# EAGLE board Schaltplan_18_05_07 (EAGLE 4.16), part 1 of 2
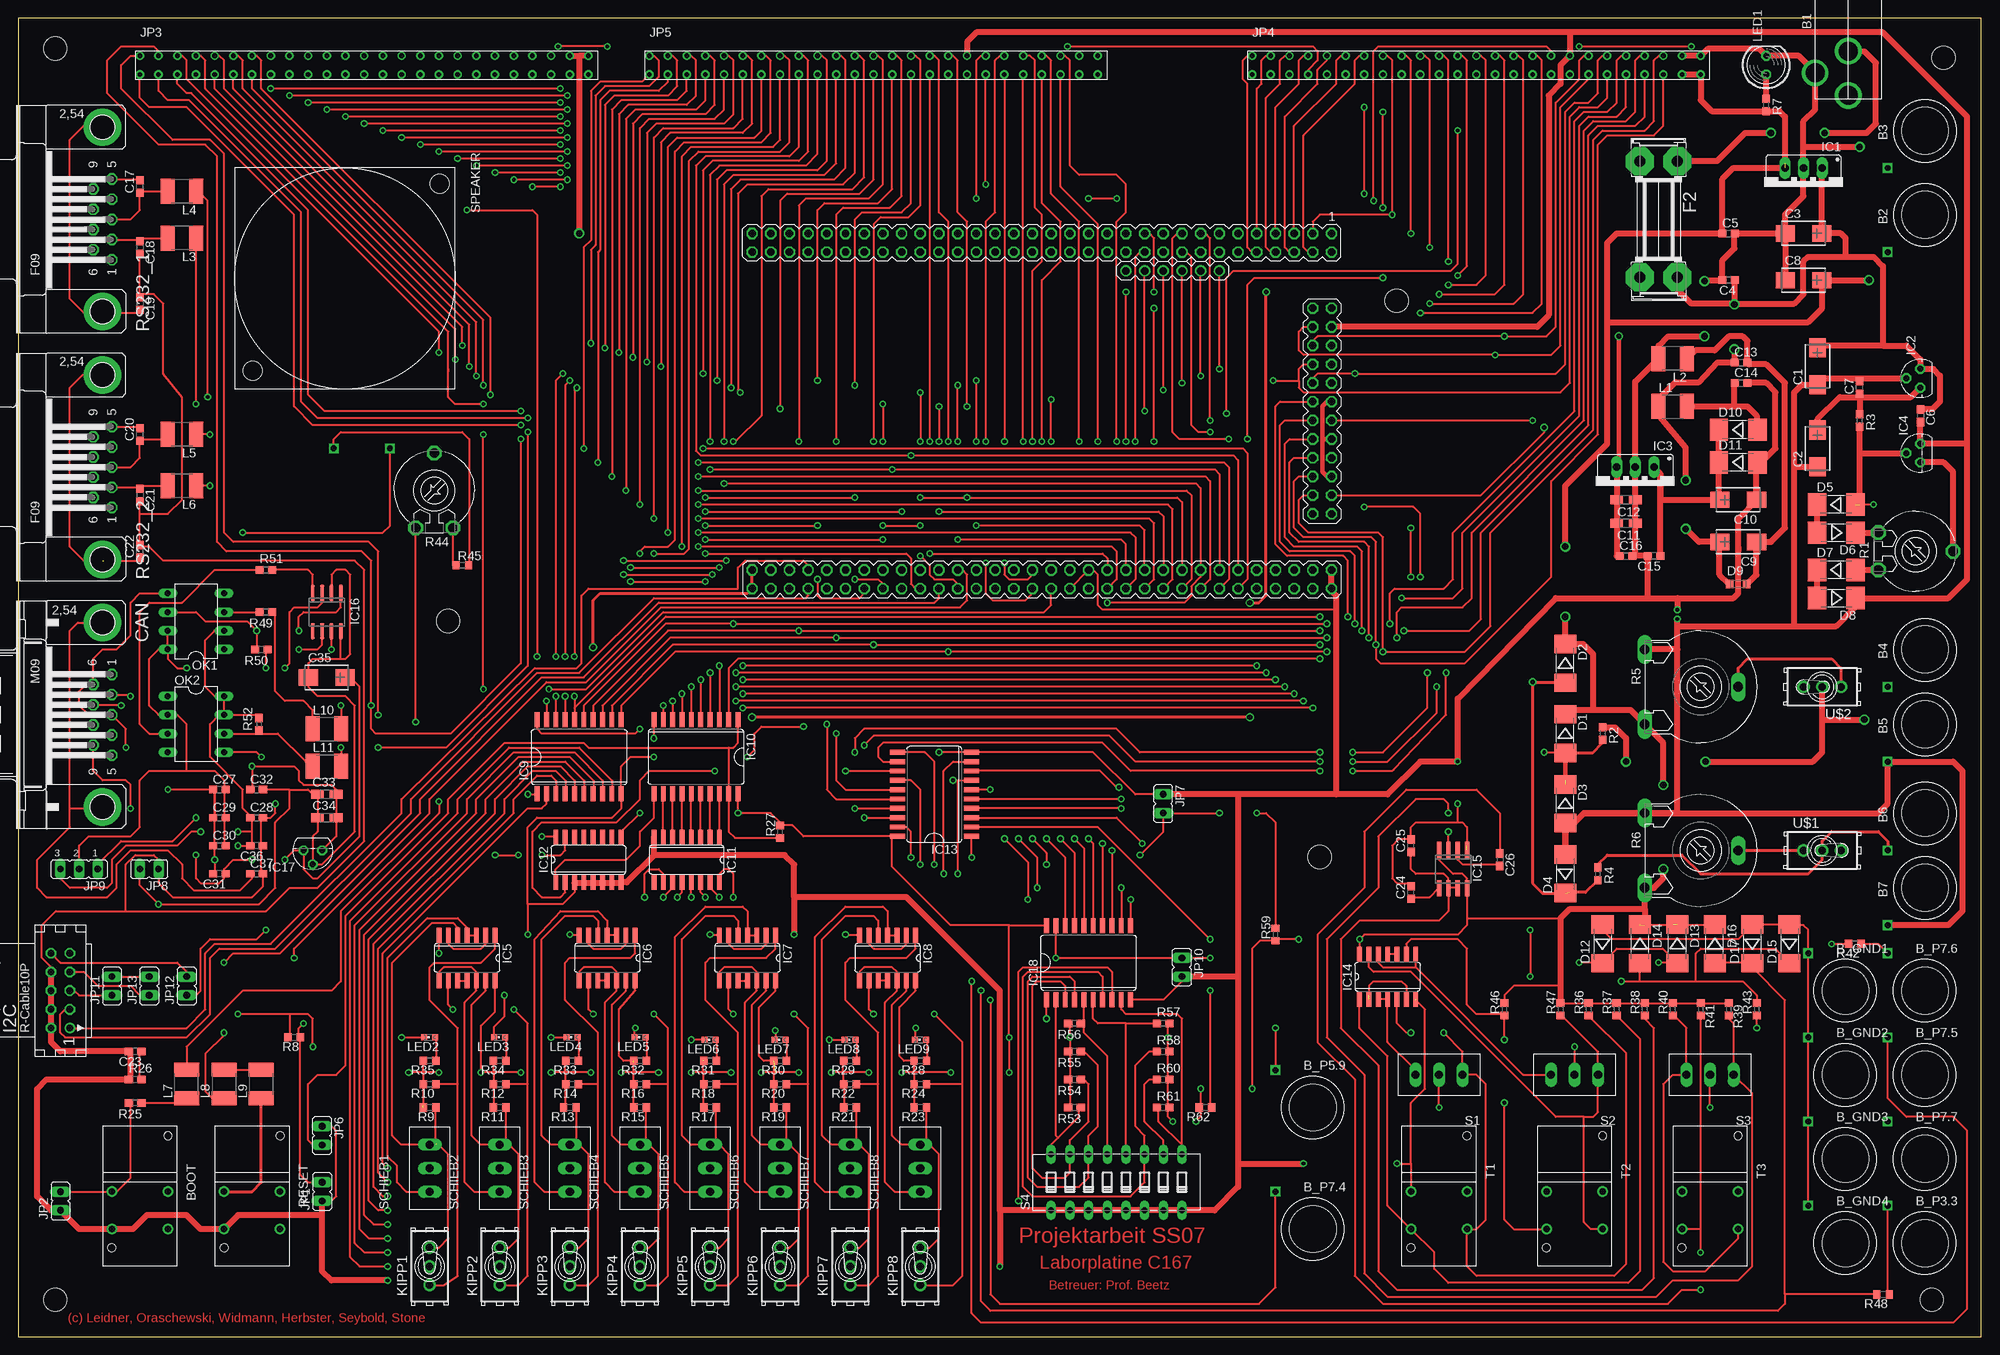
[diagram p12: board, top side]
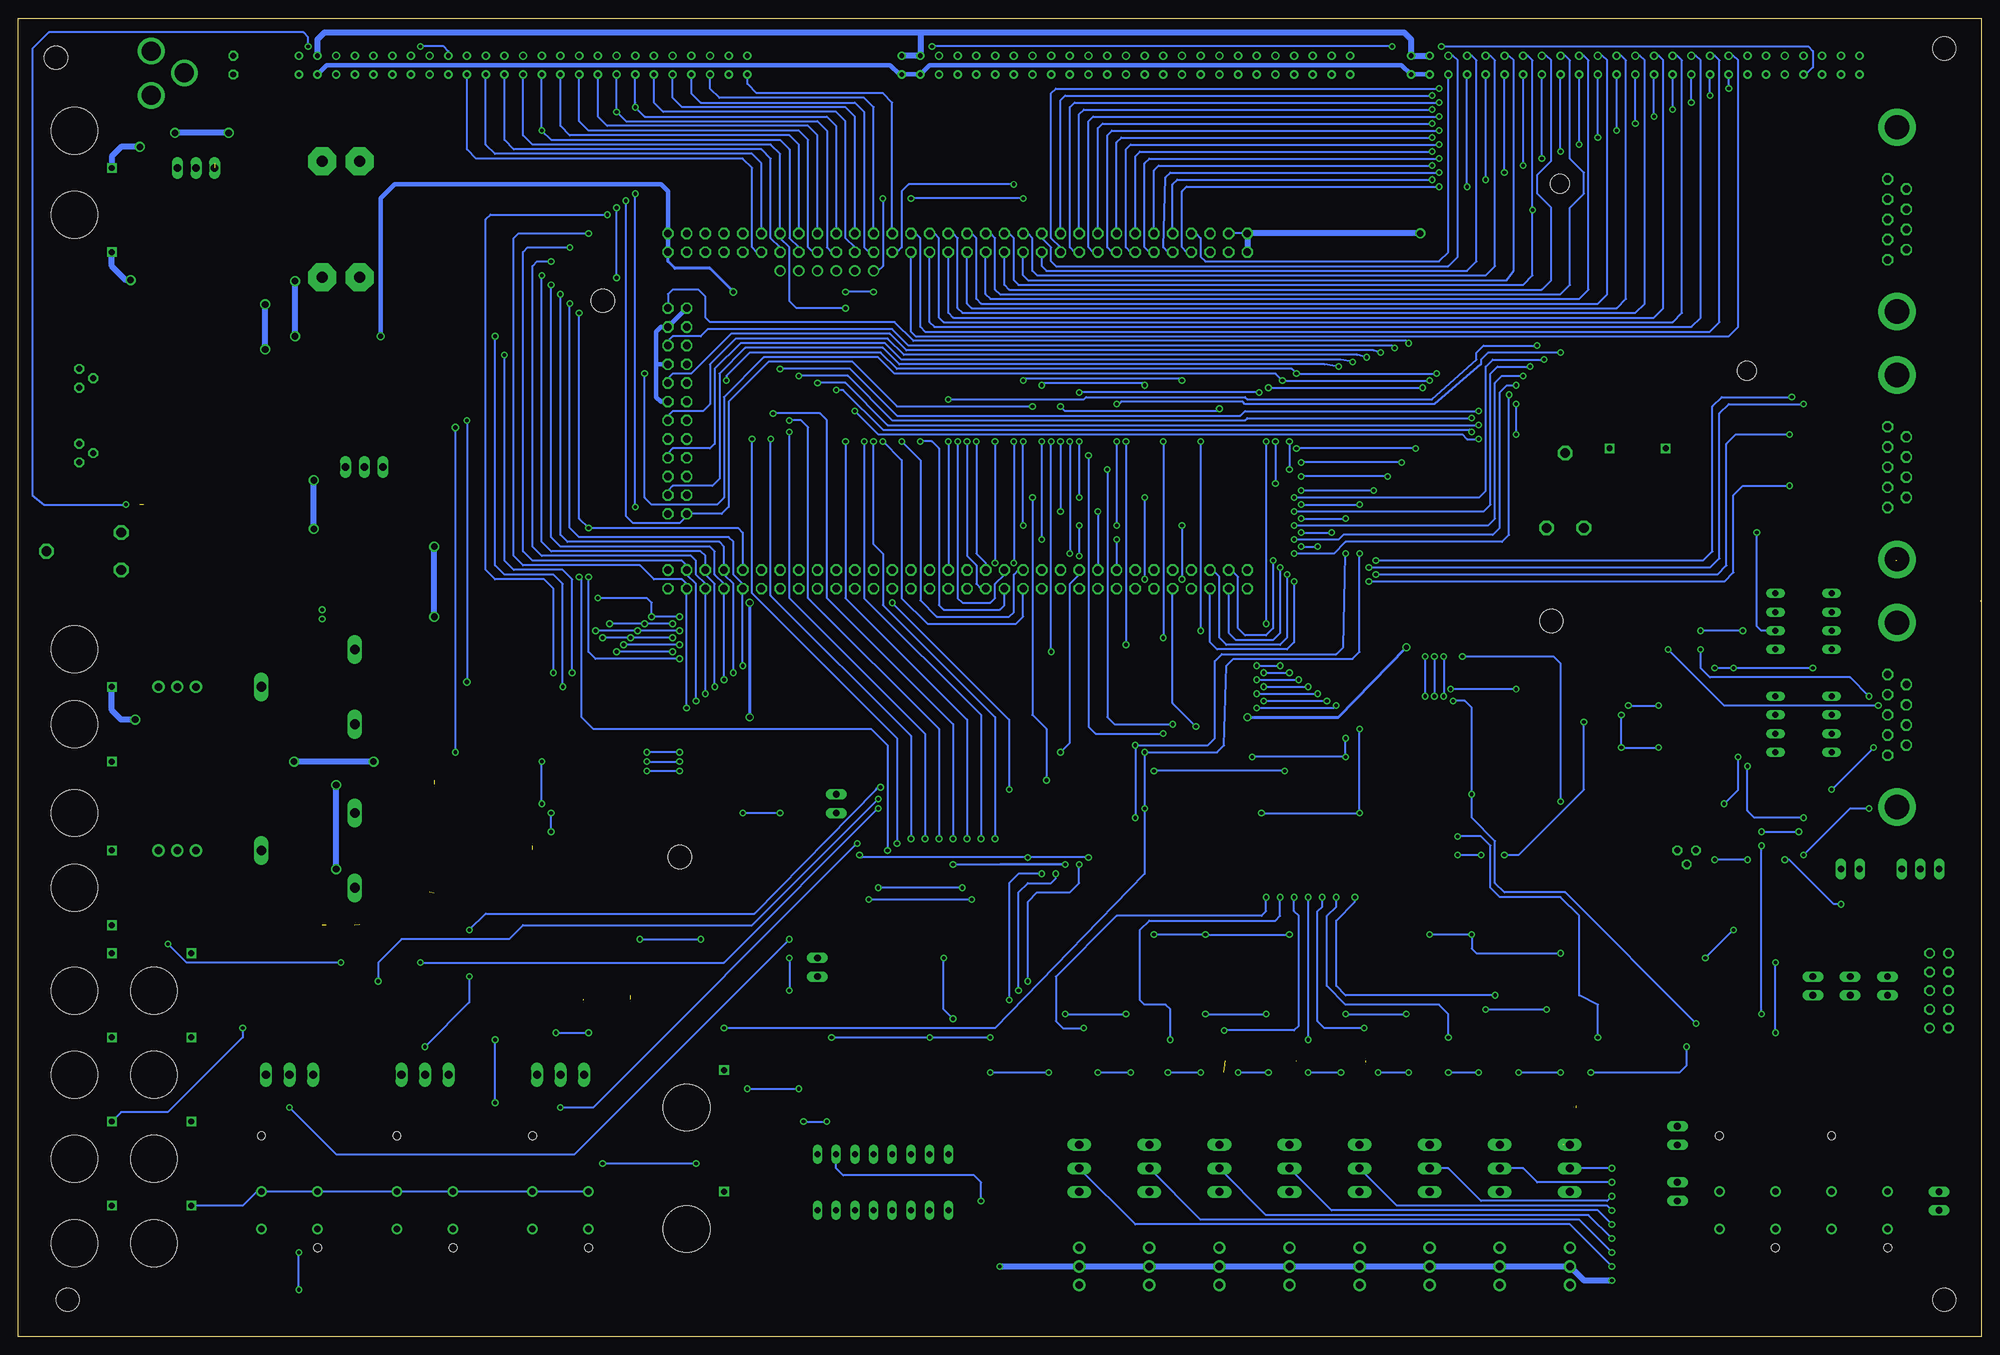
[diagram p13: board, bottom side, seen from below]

Size 266.7 x 179.07 mm. Coordinates in mm from the lower left corner, seen from the top.
Outline: 0,0 266.7,0 266.7,179.07 0,179.07 0,99.91 0.01,99.91 0,0
Copper layers (1*16): Top 0.035mm / dielectric 1.5mm / Bottom 0.035mm
Design rules "default": minimum track width 10mil, minimum drill 19mil, track to track 8mil, track to pad 8mil, pad to pad 8mil, via to via 8mil, smd to smd 8mil, copper to edge 40mil, drill to drill 8mil, minimum pad ring 10mil, minimum via ring 8mil, stop-mask expansion 4mil, vias tented up to drill 0mil, thermal gap 10mil
Holes 3.2 mm at 5,5 5,175 261.59,173.73 260,5 176.81,65.14 58.39,97.21 187.29,140.71

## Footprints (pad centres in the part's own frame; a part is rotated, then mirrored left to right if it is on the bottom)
NETZBUCHSE = drill 2.6 round: KONT -13.5,15.5; VCC+ -7.5,15.5; VCC- -10.45,20
BUCHSE01 = drill 0.8 square: 1 -5.08,5.08 | hole 6.4: 0,0
TASTER = drill 0.9 round: 1 2.54,-5.08; 2 -2.54,-5.08; 3 2.54,2.54; 4 -2.54,2.54 | hole 1.1: 5.08,-5.08; -10.16,2.54
CT6032 = smd 2.6 x 2.2: + 2.5,0; - -2.5,0
C0603 = smd 1.1 x 1: 1 -0.85,0; 2 0.85,0
R/2012-12W = smd 1.75 x 1.26: + 1.275,0; - -1.275,0
M09HP = drill 1.016 octagon: 1 -5.486,1.27; 2 -2.743,1.27; 3 0,1.27; 4 2.743,1.27; 5 5.486,1.27; 6 -4.115,-1.27; 7 -1.372,-1.27; 8 1.372,-1.27; 9 4.115,-1.27 | drill 3.302 pad 5.08 round: G1 -12.522,0; G2 12.522,0
MELF-MLL41 = smd 2.5 x 3: A 2.625,0; C -2.625,0
SOD110-W = smd 1 x 1.2: A 1.15,0; C -1.15,0
SHK20Q = drill 1.5 pad 3.81 octagon: 1A -7.874,2.54; 1B -7.874,-2.54; 2A 7.874,2.54; 2B 7.874,-2.54
CON10 = drill 0.914 round: 1 -5.08,-1.27 | drill 0.914 octagon: 2 -5.08,1.27; 3 -2.54,-1.27; 4 -2.54,1.27; 5 0,-1.27; 6 0,1.27; 7 2.54,-1.27; 8 2.54,1.27; 9 5.08,-1.27; 10 5.08,1.27
78XXS = drill 1.016 long: GND 0,-2.54; IN -2.54,-2.54; OUT 2.54,-2.54
78LXX = drill 0.813 octagon: GND 0,1.905; IN 1.27,0; OUT -1.27,0
TO92 = drill 0.813 octagon: 1 -1.27,0; 2 0,1.905; 3 1.27,0
SO14 = smd 0.66 x 2.032: 1 -3.81,-3.073; 2 -2.54,-3.073; 3 -1.27,-3.073; 4 0,-3.073; 5 1.27,-3.073; 6 2.54,-3.073; 7 3.81,-3.073; 8 3.81,3.073; 9 2.54,3.073; 10 1.27,3.073; 11 0,3.073; 12 -1.27,3.073; 13 -2.54,3.073; 14 -3.81,3.073
SO20W = smd 0.66 x 2.032: 1 -5.715,-5.029; 2 -4.445,-5.029; 3 -3.175,-5.029; 4 -1.905,-5.029; 5 -0.635,-5.029; 6 0.635,-5.029; 7 1.905,-5.029; 8 3.175,-5.029; 9 4.445,-5.029; 10 5.715,-5.029; 11 5.715,5.029; 12 4.445,5.029; 13 3.175,5.029; 14 1.905,5.029; 15 0.635,5.029; 16 -0.635,5.029; 17 -1.905,5.029; 18 -3.175,5.029; 19 -4.445,5.029; 20 -5.715,5.029
SO16 = smd 0.66 x 2.032: 1 -4.445,-3.073; 2 -3.175,-3.073; 3 -1.905,-3.073; 4 -0.635,-3.073; 5 0.635,-3.073; 6 1.905,-3.073; 7 3.175,-3.073; 8 4.445,-3.073; 9 4.445,3.073; 10 3.175,3.073; 11 1.905,3.073; 12 0.635,3.073; 13 -0.635,3.073; 14 -1.905,3.073; 15 -3.175,3.073; 16 -4.445,3.073
SO08 = smd 0.6 x 2.2: 1 -1.905,-2.6; 2 -0.635,-2.6; 3 0.635,-2.6; 4 1.905,-2.6; 5 1.905,2.6; 6 0.635,2.6; 7 -0.635,2.6; 8 -1.905,2.6
SO8 = smd 0.6 x 2.2: 1 -1.905,-2.6; 2 -0.635,-2.6; 3 0.635,-2.6; 4 1.905,-2.6; 5 1.905,2.6; 6 0.635,2.6; 7 -0.635,2.6; 8 -1.905,2.6
JP1 = drill 0.914 long: 1 0,-1.27; 2 0,1.27
CONN_50POL = drill 0.63 round: P$1 30.48,5.08; P$2 30.48,2.54; P$3 27.94,5.08; P$4 27.94,2.54; P$5 25.4,5.08; P$6 25.4,2.54; P$7 22.86,5.08; P$8 22.86,2.54; P$9 20.32,5.08; P$10 20.32,2.54; P$11 17.78,5.08; P$12 17.78,2.54; P$13 15.24,5.08; P$14 15.24,2.54; P$15 12.7,5.08; P$16 12.7,2.54; P$17 10.16,5.08; P$18 10.16,2.54; P$19 7.62,5.08; P$20 7.62,2.54; P$21 5.08,5.08; P$22 5.08,2.54; P$23 2.54,5.08; P$24 2.54,2.54; P$25 0,5.08; P$26 0,2.54; P$27 -2.54,5.08; P$28 -2.54,2.54; P$29 -5.08,5.08; P$30 -5.08,2.54; P$31 -7.62,5.08; P$32 -7.62,2.54; P$33 -10.16,5.08; P$34 -10.16,2.54; P$35 -12.7,5.08; P$36 -12.7,2.54; P$37 -15.24,5.08; P$38 -15.24,2.54; P$39 -17.78,5.08; P$40 -17.78,2.54; P$41 -20.32,5.08; P$42 -20.32,2.54; P$43 -22.86,5.08; P$44 -22.86,2.54; P$45 -25.4,5.08; P$46 -25.4,2.54; P$47 -27.94,5.08; P$48 -27.94,2.54; P$49 -30.48,5.08; P$50 -30.48,2.54
JP2 = drill 0.914 long: 1 -2.54,0; 2 0,0; 3 2.54,0
ATE1 = drill 1.016 pad 1.676 round: 1 0,-2.54; 2 0,0; 3 0,2.54
L1812 = smd 1.9 x 3.4: 1 -1.95,0; 2 1.95,0
LED5MM = drill 0.813 octagon: A -1.27,0; K 1.27,0
CHIPLED_0603 = smd 0.8 x 0.8: A 0,-0.75; C 0,0.75
MM_GES = drill 1.016 octagon: 1 -24.13,39.37; 2 -21.59,39.37; 3 -24.13,36.83; 4 -21.59,36.83; 5 -24.13,34.29; 6 -21.59,34.29; 7 -24.13,31.75; 8 -21.59,31.75; 9 -24.13,29.21; 10 -21.59,29.21; 11 -24.13,26.67; 12 -21.59,26.67; 13 -24.13,24.13; 14 -21.59,24.13; 15 -24.13,21.59; 16 -21.59,21.59; 17 -24.13,19.05; 18 -21.59,19.05; 19 -24.13,16.51; 20 -21.59,16.51; 21 -24.13,13.97; 22 -21.59,13.97; 23 -24.13,11.43; 24 -21.59,11.43; 25 -24.13,8.89; 26 -21.59,8.89; 27 -24.13,6.35; 28 -21.59,6.35; 29 -24.13,3.81; 30 -21.59,3.81; 31 -24.13,1.27; 32 -21.59,1.27; 33 -24.13,-1.27; 34 -21.59,-1.27; 35 -24.13,-3.81; 36 -21.59,-3.81; 37 -24.13,-6.35; 38 -21.59,-6.35; 39 -24.13,-8.89; 40 -21.59,-8.89; 41 -24.13,-11.43; 42 -21.59,-11.43; 43 -24.13,-13.97; 44 -21.59,-13.97; 45 -24.13,-16.51; 46 -21.59,-16.51; 47 -24.13,-19.05; 48 -21.59,-19.05; 49 -24.13,-21.59; 50 -21.59,-21.59; 51 -24.13,-24.13; 52 -21.59,-24.13; 53 -24.13,-26.67; 54 -21.59,-26.67; 55 -24.13,-29.21; 56 -21.59,-29.21; 57 -24.13,-31.75; 58 -21.59,-31.75; 59 -24.13,-34.29; 60 -21.59,-34.29; 61 -24.13,-36.83; 62 -21.59,-36.83; 63 -24.13,-39.37; 64 -21.59,-39.37; 65 24.13,-39.37; 66 21.59,-39.37; 67 24.13,-36.83; 68 21.59,-36.83; 69 24.13,-34.29; 70 21.59,-34.29; 71 24.13,-31.75; 72 21.59,-31.75; 73 24.13,-29.21; 74 21.59,-29.21; 75 24.13,-26.67; 76 21.59,-26.67; 77 24.13,-24.13; 78 21.59,-24.13; 79 24.13,-21.59; 80 21.59,-21.59; 81 24.13,-19.05; 82 21.59,-19.05; 83 24.13,-16.51; 84 21.59,-16.51; 85 24.13,-13.97; 86 21.59,-13.97; 87 24.13,-11.43; 88 21.59,-11.43; 89 24.13,-8.89; 90 21.59,-8.89; 91 24.13,-6.35; 92 21.59,-6.35; 93 24.13,-3.81; 94 21.59,-3.81; 95 24.13,-1.27; 96 21.59,-1.27; 97 24.13,1.27; 98 21.59,1.27; 99 24.13,3.81; 100 21.59,3.81; 101 24.13,6.35; 102 21.59,6.35; 103 24.13,8.89; 104 21.59,8.89; 105 24.13,11.43; 106 21.59,11.43; 107 24.13,13.97; 108 21.59,13.97; 109 24.13,16.51; 110 21.59,16.51; 111 24.13,19.05; 112 21.59,19.05; 113 24.13,21.59; 114 21.59,21.59; 115 24.13,24.13; 116 21.59,24.13; 117 24.13,26.67; 118 21.59,26.67; 119 24.13,29.21; 120 21.59,29.21; 121 24.13,31.75; 122 21.59,31.75; 123 24.13,34.29; 124 21.59,34.29; 125 24.13,36.83; 126 21.59,36.83; 127 24.13,39.37; 128 21.59,39.37; 129 13.97,39.37; 130 13.97,36.83; 131 11.43,39.37; 132 11.43,36.83; 133 8.89,39.37; 134 8.89,36.83; 135 6.35,39.37; 136 6.35,36.83; 137 3.81,39.37; 138 3.81,36.83; 139 1.27,39.37; 140 1.27,36.83; 141 -1.27,39.37; 142 -1.27,36.83; 143 -3.81,39.37; 144 -3.81,36.83; 145 -6.35,39.37; 146 -6.35,36.83; 147 -8.89,39.37; 148 -8.89,36.83; 149 -11.43,39.37; 150 -11.43,36.83; 151 -13.97,39.37; 152 -13.97,36.83 | drill 1.016 round: 153 -19.05,24.13; 154 -19.05,21.59; 155 -19.05,19.05; 156 -19.05,16.51; 157 -19.05,13.97; 158 -19.05,11.43
DIL08 = drill 0.813 long: 1 -3.81,-3.81; 2 -1.27,-3.81; 3 1.27,-3.81; 4 3.81,-3.81; 5 3.81,3.81; 6 1.27,3.81; 7 -1.27,3.81; 8 -3.81,3.81
LI10 = drill 1.321 octagon: A -2.54,-5.08; E 2.54,-5.08; S 0,5.08
R0603 = smd 1.1 x 1: 1 -0.85,0; 2 0.85,0
LI15 = drill 1.321 long: A -5.08,-7.62; E 5.08,-7.62; S 0,5.08
R0603' = smd 1 x 1.1: 1 -0.85,0; 2 0.85,0
F09HP = drill 1.016 octagon: 1 -5.486,-1.27; 2 -2.743,-1.27; 3 0,-1.27; 4 2.743,-1.27; 5 5.486,-1.27; 6 -4.115,1.27; 7 -1.372,1.27; 8 1.372,1.27; 9 4.115,1.27 | drill 3.302 pad 5.08 round: G1 -12.522,0; G2 12.522,0
SCHIEBESCHALTER = drill 1.1 long: P$1 -3.2,0; P$2 0,0; P$3 3.2,0
DIP08YL = drill 0.813 long: 1 -8.89,-3.81; 2 -6.35,-3.81; 3 -3.81,-3.81; 4 -1.27,-3.81; 5 1.27,-3.81; 6 3.81,-3.81; 7 6.35,-3.81; 8 8.89,-3.81; 9 8.89,3.81; 10 6.35,3.81; 11 3.81,3.81; 12 1.27,3.81; 13 -1.27,3.81; 14 -3.81,3.81; 15 -6.35,3.81; 16 -8.89,3.81
LAUTSPRECHER = drill 0.8 square: + 38.1,-8.89; - 38.1,-16.51 | hole 2.6: 2.12,-2.12; 27.56,-27.56

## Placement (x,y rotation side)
B1  NETZBUCHSE  [NETZBUCHSE]  264.16,182.12 90 top
B2  BUCHSE01  [BUCHSE01]  259.08,152.4 90 top
B3  BUCHSE01  [BUCHSE01]  259.08,163.83 90 top
B4  BUCHSE01  [BUCHSE01]  259.08,93.34 90 top
B5  BUCHSE01  [BUCHSE01]  259.08,83.19 90 top
B6  BUCHSE01  [BUCHSE01]  259.08,71.12 90 top
B7  BUCHSE01  [BUCHSE01]  259.08,60.96 90 top
B_GND1  BUCHSE01  [BUCHSE01]  248.28,46.99 0 top
B_GND2  BUCHSE01  [BUCHSE01]  248.28,35.56 0 top
B_GND3  BUCHSE01  [BUCHSE01]  248.28,24.13 0 top
B_GND4  BUCHSE01  [BUCHSE01]  248.28,12.7 0 top
B_P3.3  BUCHSE01  [BUCHSE01]  259.08,12.7 0 top
B_P5.9  Buchse P5.9  [BUCHSE01]  175.9,31.11 0 top
B_P7.4  BUCHSE01  [BUCHSE01]  175.9,14.61 0 top
B_P7.5  BUCHSE01  [BUCHSE01]  259.08,35.56 0 top
B_P7.6  BUCHSE01  [BUCHSE01]  259.08,46.99 0 top
B_P7.7  BUCHSE01  [BUCHSE01]  259.08,24.13 0 top
BOOT  TASTER  [TASTER]  17.78,17.14 270 top
C1  1µ  [CT6032]  244.47,131.83 90 top
C2  1µ  [CT6032]  244.47,120.65 90 top
C3  100µ  [CT6032]  242.57,149.86 0 top
C4  10n  [C0603]  232.41,143.51 180 top
C5  10n  [C0603]  232.41,149.86 0 top
C6  1n  [C0603]  258.44,125.09 270 top
C7  1n  [C0603]  250.19,128.91 90 top
C8  100µ  [CT6032]  242.57,143.51 0 top
C9  10µ  [CT6032]  233.68,107.95 180 top
C10  10µ  [CT6032]  233.68,113.67 180 top
C11  4,7µ  [R/2012-12W]  218.44,110.49 180 top
C12  4,7µ  [R/2012-12W]  218.44,113.67 180 top
C13  100n  [C0603]  234.06,132.33 0 top
C14  100n  [C0603]  234.06,129.54 0 top
C15  100n  [C0603]  222.25,106.05 180 top
C16  100n  [C0603]  218.44,106.05 0 top
C17  22pF  [C0603]  16.51,156.21 90 top
C18  22pF  [C0603]  16.51,147.96 270 top
C19  100nF  [C0603]  16.51,140.34 270 top
C20  22pF  [C0603]  16.51,122.56 90 top
C21  22pF  [C0603]  16.51,114.3 270 top
C22  100nF  [C0603]  16.51,106.68 90 top
C23  100n  [C0603]  15.88,38.73 180 top
C24  10nF  [C0603]  189.23,60.33 90 top
C25  10nF  [C0603]  189.23,66.67 90 top
C26  1uF  [C0603]  201.29,64.77 270 top
C27  100n  [C0603]  27.3,74.3 0 top
C28  100n  [C0603]  32.38,70.48 0 top
C29  100n  [C0603]  27.3,70.48 0 top
C30  100n  [C0603]  27.3,66.67 0 top
C31  100n  [C0603]  27.3,62.87 180 top
C32  100n  [C0603]  32.38,74.3 0 top
C33  4u7/6  [R/2012-12W]  41.91,73.66 0 top
C34  4u7/6  [R/2012-12W]  41.91,70.48 0 top
C35  10u/25  [CT6032]  41.91,89.53 0 top
C36  100n  [C0603]  32.38,66.67 180 top
C37  100n  [C0603]  32.38,62.87 0 top
CAN  [M09HP]  11.43,84.45 270 top
D1  1N4001  [MELF-MLL41]  210.19,81.92 270 top
D2  1N4001  [MELF-MLL41]  210.19,91.44 270 top
D3  1N4001  [MELF-MLL41]  210.19,72.39 270 top
D4  1N4001  [MELF-MLL41]  210.19,62.87 90 top
D5  1N4148  [MELF-MLL41]  247.01,113.03 0 top
D6  1N4148  [MELF-MLL41]  247.01,109.22 180 top
D7  1N4148  [MELF-MLL41]  247.01,104.14 0 top
D8  1N4148  [MELF-MLL41]  247.01,100.33 180 top
D9  [SOD110-W]  233.68,102.23 0 top
D10  4001  [MELF-MLL41]  233.68,123.19 0 top
D11  4001  [MELF-MLL41]  233.68,118.75 0 top
D12  1N4001  [MELF-MLL41]  215.26,53.34 90 top
D13  1N4001  [MELF-MLL41]  225.43,53.34 270 top
D14  1N4001  [MELF-MLL41]  220.34,53.34 270 top
D15  1N4001  [MELF-MLL41]  240.66,53.34 90 top
D16  1N4001  [MELF-MLL41]  230.5,53.34 270 top
D17  1N4001  [MELF-MLL41]  235.59,53.34 90 top
F2  [SHK20Q]  222.88,151.76 270 top
I2C  [CON10]  5.71,46.99 90 top
IC1  7805T  [78XXS]  242.57,156.21 180 top
IC2  [78LXX]  258.44,130.18 90 top
IC3  7805T  [78XXS]  219.71,115.57 180 top
IC4  7805L  [TO92]  258.44,120.02 90 top
IC5  74S00D  [SO14]  60.96,51.44 180 top
IC6  74S00D  [SO14]  80.01,51.44 180 top
IC7  74S00D  [SO14]  99.06,51.44 180 top
IC8  74S00D  [SO14]  118.11,51.44 180 top
IC9  74LS541DW  [SO20W]  76.2,78.74 0 top
IC10  74LS541DW  [SO20W]  92.08,78.74 180 top
IC11  ULN2003AD  [SO16]  90.81,64.77 180 top
IC12  ULN2003AD  [SO16]  77.47,64.77 0 top
IC13  74LS541DW  [SO20W]  124.46,73.66 90 top
IC14  74S00D  [SO14]  186.06,48.9 0 top
IC15  NE555D  [SO08]  194.94,63.5 180 top
IC16  PCA82C250T/N4  [SO8]  41.91,98.42 180 top
IC17  78L05  [TO92]  40.01,66.04 180 top
IC18  74LS541DW  [SO20W]  145.41,50.8 0 top
JP1  [JP1]  41.27,19.68 0 top
JP2  [JP1]  5.71,18.41 0 top
JP3  CONN_50POL  [CONN_50POL]  46.99,168.91 0 top
JP4  CONN_50POL  [CONN_50POL]  198.12,168.91 0 top
JP5  CONN_50POL  [CONN_50POL]  116.2,168.91 0 top
JP6  [JP1]  41.27,27.3 180 top
JP7  [JP1]  155.57,72.39 180 top
JP8  [JP1]  17.78,63.5 90 top
JP9  [JP2]  8.26,63.5 180 top
JP10  [JP1]  158.12,50.16 180 top
JP11  [JP1]  12.7,47.62 0 top
JP12  [JP1]  22.86,47.62 0 top
JP13  [JP1]  17.78,47.62 0 top
KIPP1  ATE1  [ATE1]  55.88,9.53 0 top
KIPP2  ATE1  [ATE1]  65.41,9.53 0 top
KIPP3  ATE1  [ATE1]  74.93,9.53 0 top
KIPP4  ATE1  [ATE1]  84.45,9.53 0 top
KIPP5  ATE1  [ATE1]  93.98,9.53 0 top
KIPP6  ATE1  [ATE1]  103.5,9.53 0 top
KIPP7  ATE1  [ATE1]  113.03,9.53 0 top
KIPP8  ATE1  [ATE1]  122.56,9.53 0 top
L1  2,2µ  [L1812]  224.79,126.36 0 top
L2  2,2µ  [L1812]  224.79,132.84 180 top
L3  2u2  [L1812]  22.23,149.22 180 top
L4  2u2  [L1812]  22.23,155.57 180 top
L5  2u2  [L1812]  22.23,122.56 180 top
L6  2u2  [L1812]  22.23,115.57 180 top
L7  2u2  [L1812]  22.86,34.29 90 top
L8  2u2  [L1812]  27.94,34.29 270 top
L9  2u2  [L1812]  33.02,34.29 90 top
L10  2u2  [L1812]  41.91,82.55 0 top
L11  2u2  [L1812]  41.91,77.47 0 top
LED1  [LED5MM]  237.49,172.72 90 top
LED2  [CHIPLED_0603]  55.88,40.64 90 top
LED3  [CHIPLED_0603]  65.41,40.64 90 top
LED4  [CHIPLED_0603]  75.25,40.64 90 top
LED5  [CHIPLED_0603]  84.45,40.64 90 top
LED6  [CHIPLED_0603]  93.98,40.32 90 top
LED7  [CHIPLED_0603]  103.5,40.32 90 top
LED8  [CHIPLED_0603]  113.03,40.32 90 top
LED9  [CHIPLED_0603]  122.56,40.32 90 top
MM_C1  [MM_GES]  139.06,125.73 270 top
OK1  6N137  [DIL08]  24.13,97.16 90 top
OK2  6N137  [DIL08]  24.13,83.19 270 top
R1  [LI10]  257.81,106.68 270 top
R2  1000  [R0603]  215.26,81.92 270 top
R3  2k  [R0603]  250.19,124.46 270 top
R4  1000  [R0603]  214.63,62.87 270 top
R5  [LI15]  228.6,88.27 270 top
R6  [LI15]  228.6,66.04 270 top
R7  56R  [R0603]  237.49,167.32 270 top
R8  10k  [R0603']  37.47,40.64 180 top
R9  3.3k  [R0603']  55.88,31.11 180 top
R10  3.3k  [R0603']  55.88,34.29 180 top
R11  3.3k  [R0603']  65.41,31.11 180 top
R12  3.3k  [R0603']  65.41,34.29 180 top
R13  3.3k  [R0603']  74.93,31.11 180 top
R14  3.3k  [R0603']  75.25,34.29 180 top
R15  3.3k  [R0603']  84.45,31.11 180 top
R16  3.3k  [R0603']  84.45,34.29 180 top
R17  3.3k  [R0603']  93.98,31.11 180 top
R18  3.3k  [R0603']  93.98,34.29 180 top
R19  3.3k  [R0603']  103.5,31.11 180 top
R20  3.3k  [R0603']  103.5,34.29 180 top
R21  3.3k  [R0603']  113.03,31.11 180 top
R22  3.3k  [R0603']  113.03,34.29 180 top
R23  3.3k  [R0603']  122.56,31.11 180 top
R24  3.3k  [R0603']  122.56,34.29 180 top
R25  10k  [R0603]  15.88,31.75 180 top
R26  4k7  [R0603]  15.88,34.92 0 top
R27  10k  [R0603']  103.5,68.58 90 top
R28  220R  [R0603']  122.56,37.47 180 top
R29  220R  [R0603']  113.03,37.47 180 top
R30  220R  [R0603']  103.5,37.47 180 top
R31  220R  [R0603']  93.98,37.47 180 top
R32  220R  [R0603']  84.45,37.47 180 top
R33  220R  [R0603']  75.25,37.47 180 top
R34  220R  [R0603']  65.41,37.47 180 top
R35  220R  [R0603']  55.88,37.47 180 top
R36  3.3k  [R0603']  213.36,44.45 90 top
R37  3.3k  [R0603']  217.17,44.45 90 top
R38  9,1k  [R0603']  220.98,44.45 90 top
R39  2,2k  [R0603']  232.41,44.45 270 top
R40  3,3k  [R0603']  224.79,44.45 90 top
R41  3,3k  [R0603']  228.6,44.45 270 top
R42  1K  [R0603']  249.56,53.34 180 top
R43  1k  [R0603']  236.22,44.45 90 top
R44  [LI10]  56.52,114.94 0 top
R45  27R  [R0603']  60.33,104.78 0 top
R46  3.3k  [R0603']  201.93,44.45 90 top
R47  3.3k  [R0603']  209.55,44.45 90 top
R48  1K  [R0603']  253.37,5.71 180 top
R49  390R  [R0603]  33.66,98.42 180 top
R50  390R  [R0603]  33.02,93.34 180 top
R51  390R  [R0603]  33.66,104.14 0 top
R52  390R  [R0603]  32.7,83.19 90 top
R53  3.3k  [R0603]  143.51,31.11 180 top
R54  3.3k  [R0603]  143.51,34.92 180 top
R55  3.3k  [R0603]  143.51,38.73 180 top
R56  3.3k  [R0603]  143.51,42.55 180 top
R57  3.3k  [R0603]  155.57,42.55 0 top
R58  3.3k  [R0603]  155.57,38.73 0 top
R59  10K  [R0603']  170.81,54.61 90 top
R60  3.3k  [R0603]  155.57,34.92 0 top
R61  3.3k  [R0603]  155.57,31.11 0 top
R62  [R0603']  161.29,31.11 180 top
RESET  TASTER  [TASTER]  33.02,17.14 270 top
RS232_1  [F09HP]  11.43,151.76 90 top
RS232_2  [F09HP]  11.43,118.11 90 top
S1  SCHIEBESCHALTER_WECHSLER  [SCHIEBESCHALTER]  193.04,35.56 180 top
S2  SCHIEBESCHALTER_WECHSLER  [SCHIEBESCHALTER]  211.46,35.56 180 top
S3  SCHIEBESCHALTER_WECHSLER  [SCHIEBESCHALTER]  229.87,35.56 180 top
S4  [DIP08YL]  149.22,20.95 0 top
SCHIEB1  SCHIEBESCHALTER_WECHSLER  [SCHIEBESCHALTER]  55.9,22.86 90 top
SCHIEB2  SCHIEBESCHALTER_WECHSLER  [SCHIEBESCHALTER]  65.41,22.86 90 top
SCHIEB3  SCHIEBESCHALTER_WECHSLER  [SCHIEBESCHALTER]  74.93,22.86 90 top
SCHIEB4  SCHIEBESCHALTER_WECHSLER  [SCHIEBESCHALTER]  84.45,22.86 90 top
SCHIEB5  SCHIEBESCHALTER_WECHSLER  [SCHIEBESCHALTER]  93.98,22.86 90 top
SCHIEB6  SCHIEBESCHALTER_WECHSLER  [SCHIEBESCHALTER]  103.5,22.86 90 top
SCHIEB7  SCHIEBESCHALTER_WECHSLER  [SCHIEBESCHALTER]  113.03,22.86 90 top
SCHIEB8  SCHIEBESCHALTER_WECHSLER  [SCHIEBESCHALTER]  122.56,22.86 90 top
SPEAKER  LAUTSPRECHER  [LAUTSPRECHER]  59.37,158.75 270 top
T1  TASTER  [TASTER]  194.31,17.14 270 top
T2  TASTER  [TASTER]  212.72,17.14 270 top
T3  TASTER  [TASTER]  231.14,17.14 270 top
U$1  ATE1  [ATE1]  245.11,66.04 270 top
U$2  ATE1  [ATE1]  245.11,88.27 90 top

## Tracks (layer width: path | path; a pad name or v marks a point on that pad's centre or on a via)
/IRTC  (via drill 0.5 pad 0.3)
  Top 0.305: JP12.1 24.13,46.35 24.77,46.99 24.77,52.7 26.04,53.98 32.38,53.98 v33.66,55.24 | MM_C1.88 128.27,104.14 128.91,103.5 128.91,100.01 127.95,99.06 87.31,99.06 77.15,88.9 71.75,88.9 55.88,73.03 55.88,71.12 37.47,52.7 v37.47,51.44
  Bottom 0.305: v33.66,55.24 v37.47,51.44
/NMI  (via drill 0.5 pad 0.3)
  Top 0.305: MM_C1.87 127.64,102.23 127,102.87 124.46,102.87 123.83,103.5 123.83,104.78 v122.56,106.05 | v117.47,110.17 v122.56,110.17 | v117.47,126.68 v117.47,121.6 | v57.15,133.67 57.15,136.53 22.86,170.81 22.86,173.35 22.23,173.99 JP3.P$45
  Bottom 0.305: v122.56,110.17 v122.56,106.05 | v117.47,121.6 v117.47,110.17 | v117.47,126.68 117.16,126.68 116.84,127 100.33,127 100.01,126.68 74.3,126.68 67.94,132.08 67.94,132.72 66.99,133.67 v57.15,133.67
/RD  (via drill 0.5 pad 0.3)
  Top 0.305: JP3.P$37 32.38,173.99 33.02,173.35 33.02,169.54 64.14,138.43 v64.14,127.95 | v93.34,106.36 120.65,106.36 121.28,105.73 121.28,102.23 121.92,101.6 MM_C1.83
  Bottom 0.305: v64.14,127.95 64.14,108.9 65.09,107.95 86.36,107.95 87.95,106.36 v93.34,106.36
/RDY  (via drill 0.5 pad 0.81)
  Top 0.305: v131.44,156.53 JP5.P$14
  Bottom 0.305: v131.44,156.53 145.73,156.53 146.69,155.57 146.69,147.96 147.32,147.32 MM_C1.26
/RES  (via drill 0.5 pad 0.3)
  Top 0.305: v27.94,41.27 27.94,40.96 25.4,38.42 25.4,33.34 26.35,32.38 | v27.94,50.8 29.21,52.07 35.56,52.07 54.61,71.12 54.61,73.03 71.12,89.53 76.83,89.53 87,99.69 124.46,99.69 125.09,100.33 MM_C1.85
  Top 0.406: L8.2 27.94,32.38 26.35,32.38
  Bottom 0.305: v27.94,41.27 v27.94,50.8
/RESI  (via drill 0.5 pad 0.3)
  Top 0.305: v140.34,121.6 v140.34,127.32 | v60.33,134.62 60.33,137.16 27.94,169.54 27.94,173.35 27.3,173.99 JP3.P$41
  Bottom 0.305: v140.34,121.6 MM_C1.98 | v140.34,127.32 121.92,127.32 121.6,127.64 100.01,127.64 99.69,127.32 74.61,127.32 68.58,132.72 68.58,133.67 67.63,134.62 v60.33,134.62
/RESO  (via drill 0.5 pad 0.3)
  Top 0.305: MM_C1.97 140.34,99.38 139.38,98.42 87.63,98.42 77.15,87.95 v72.07,87.95 | 58.42,131.44 58.42,131.13 | 58.42,131.44 58.42,136.53 25.4,169.54 25.4,173.35 24.77,173.99 JP3.P$43 | 58.42,131.44 58.42,127.64 59.37,126.68 v63.18,126.68 | v63.18,87.95 v63.18,122.56
  Bottom 0.305: v63.18,87.95 v72.07,87.95 | v63.18,122.56 v63.18,126.68
/WR  (via drill 0.5 pad 0.3)
  Top 0.305: MM_C1.79 117.47,102.23 116.84,102.87 v113.67,102.87 | v93.34,113.98 v113.67,113.98 | v59.37,132.72 59.37,136.84 26.67,169.54 JP3.P$42
  Bottom 0.305: v113.67,113.98 v113.67,102.87 | v93.34,113.98 68.26,113.98 67.31,114.94 67.31,131.76 66.36,132.72 v59.37,132.72
A0
  Bottom 0.305: JP3.P$6 72.39,147.32 73.66,146.05 105.41,146.05 106.05,146.69 106.05,149.22 106.68,149.86 MM_C1.57
A1  (via drill 0.5 pad 0.3)
  Top 0.305: v73.66,156.21 v69.85,156.21
  Bottom 0.305: v69.85,156.21 JP3.P$8 | v73.66,156.21 107.95,156.21 108.58,155.57 108.58,147.96 107.95,147.32 MM_C1.58
A2  (via drill 0.5 pad 0.3)
  Top 0.305: v74.61,157.16 v67.31,157.16
  Bottom 0.305: v67.31,157.16 JP3.P$10 | v74.61,157.16 109.22,157.16 109.86,156.53 MM_C1.55
A3  (via drill 0.5 pad 0.3)
  Top 0.305: v73.66,158.12 v64.77,158.12
  Bottom 0.305: v64.77,158.12 JP3.P$12 | v73.66,158.12 110.17,158.12 110.81,157.48 111.12,147.96 110.49,147.32 MM_C1.56
A4  (via drill 0.5 pad 0.3)
  Top 0.305: v74.61,159.07 v62.23,159.07
  Bottom 0.305: v62.23,159.07 JP3.P$14 | v74.61,159.07 111.76,159.07 112.39,158.43 MM_C1.53
A5  (via drill 0.5 pad 0.3)
  Top 0.305: v73.66,160.02 v59.69,160.02
  Bottom 0.305: v59.69,160.02 JP3.P$16 | v73.66,160.02 113.03,160.02 113.67,159.38 113.67,147.96 113.03,147.32 MM_C1.54
A6  (via drill 0.5 pad 0.3)
  Top 0.305: v74.61,160.97 v57.15,160.97
  Bottom 0.305: v57.15,160.97 JP3.P$18 | v74.61,160.97 114.3,160.97 114.94,160.34 MM_C1.51
A7  (via drill 0.5 pad 0.3)
  Top 0.305: v73.66,161.93 v54.61,161.93
  Bottom 0.305: v54.61,161.93 JP3.P$20 | v73.66,161.93 115.57,161.93 116.2,161.29 116.2,147.96 115.57,147.32 MM_C1.52
A8  (via drill 0.5 pad 0.3)
  Top 0.305: v74.61,162.88 v52.07,162.88
  Bottom 0.305: v52.07,162.88 JP3.P$22 | v74.61,162.88 116.84,162.88 117.47,162.24 MM_C1.49
A9  (via drill 0.5 pad 0.3)
  Top 0.305: v73.66,163.83 v49.53,163.83
  Bottom 0.305: v49.53,163.83 JP3.P$24 | v73.66,163.83 118.11,163.83 118.75,163.19 118.75,147.96 118.11,147.32 MM_C1.50
A10  (via drill 0.5 pad 0.3)
  Top 0.305: v74.61,164.78 v46.99,164.78
  Bottom 0.305: v46.99,164.78 JP3.P$26 | v74.61,164.78 119.38,164.78 120.02,164.15 MM_C1.47
A11  (via drill 0.5 pad 0.3)
  Top 0.305: v73.66,165.74 v44.45,165.74
  Bottom 0.305: v44.45,165.74 JP3.P$28 | v73.66,165.74 120.65,165.74 121.28,165.1 121.28,147.96 120.65,147.32 MM_C1.48
A12  (via drill 0.5 pad 0.3)
  Top 0.305: v74.61,166.69 v41.91,166.69
  Bottom 0.305: v41.91,166.69 JP3.P$30 | v74.61,166.69 121.92,166.69 122.56,166.05 MM_C1.45
A13  (via drill 0.5 pad 0.3)
  Top 0.305: v73.66,167.64 v39.37,167.64
  Bottom 0.305: v39.37,167.64 JP3.P$32 | v73.66,167.64 123.19,167.64 123.83,167 123.83,147.96 123.19,147.32 MM_C1.46
A14  (via drill 0.5 pad 0.3)
  Top 0.305: v74.61,168.59 v36.83,168.59
  Bottom 0.305: v36.83,168.59 JP3.P$34 | v74.61,168.59 124.46,168.59 125.09,167.96 MM_C1.43
A15  (via drill 0.5 pad 0.3)
  Top 0.305: v73.66,169.54 v34.29,169.54
  Bottom 0.305: v34.29,169.54 JP3.P$36 | v73.66,169.54 125.73,169.54 126.36,168.91 126.36,149.22 125.09,147.96 MM_C1.44
A16  (via drill 0.5 pad 0.3)
  Top 0.305: JP3.P$38 31.75,169.54 63.18,138.11 v63.18,129.22 | v93.34,108.27 v117.47,108.27
  Bottom 0.305: v63.18,129.22 64.45,129.22 65.41,128.27 65.41,109.86 66.36,108.9 86.68,108.9 87.31,108.27 v93.34,108.27 | v117.47,108.27 MM_C1.80
A17  (via drill 0.5 pad 0.3)
  Top 0.305: JP3.P$40 29.21,169.54 61.28,137.48 v61.28,131.76 | v93.34,112.08 v120.02,112.08
  Bottom 0.305: v61.28,131.76 65.72,131.76 66.67,130.81 66.67,113.03 67.63,112.08 v93.34,112.08 | v120.02,112.08 MM_C1.82
A18  (via drill 0.5 pad 0.3)
  Top 0.305: JP3.P$46 21.59,170.18 22.86,168.91 23.5,168.91 39.37,153.03 39.37,127.95 41.59,125.73 v68.26,125.73 | v163.19,131.44 MM_C1.153
  Bottom 0.305: v68.26,125.73 100.01,125.73 100.65,125.09 147.32,125.09 153.67,131.44 v163.19,131.44
A19  (via drill 0.5 pad 0.3)
  Top 0.305: JP3.P$48 19.05,169.23 20.32,167.96 23.18,167.96 38.42,152.72 38.42,127 40.64,124.78 v69.22,124.78 | v160.66,130.49 MM_C1.154
  Bottom 0.305: v69.22,124.78 99.69,124.78 100.01,124.46 147.96,124.46 153.99,130.49 v160.66,130.49
A20  (via drill 0.5 pad 0.3)
  Top 0.305: JP3.P$50 16.51,168.28 17.78,167 22.86,167 37.47,152.4 37.47,126.36 40.01,123.83 v68.26,123.83 | v158.12,129.54 MM_C1.155
  Bottom 0.305: v68.26,123.83 148.59,123.83 154.31,129.54 v158.12,129.54
A21  (via drill 0.5, 0.5 pad 0.3)
  Top 0.305: L11.2 43.86,79.97 v43.81,80.01 | JP3.P$49 15.24,173.99 13.97,172.72 13.97,169.54 20.95,162.56 26.04,162.56 27.94,160.66 27.94,109.22 29.21,107.95 47.62,107.95 48.9,106.68 v48.9,84.45 | v155.57,128.59 MM_C1.156 | v69.22,122.87 69.22,91.12 58.1,80.01 v48.9,80.01
  Bottom 0.305: v48.9,84.45 v48.9,80.01 v43.81,80.01 | v155.57,128.59 154.62,128.59 149.22,123.19 69.53,123.19 v69.22,122.87
A22  (via drill 0.5, 0.5 pad 0.3)
  Top 0.305: 43.81,82.55 L10.2 43.86,85.68 v43.81,85.72 | JP3.P$47 19.05,174.62 18.41,175.26 13.97,175.26 12.06,173.35 12.06,168.91 19.05,161.93 25.4,161.93 26.99,160.34 26.99,107.95 28.26,106.68 46.67,106.68 47.94,105.41 v47.94,85.72 47.94,82.55 48.58,81.92 58.74,81.92 68.26,91.44 v68.26,121.92 | v153.03,125.73 MM_C1.157
  Bottom 0.305: v47.94,85.72 v43.81,85.72 | v153.03,125.73 149.86,122.56 70.48,122.56 69.85,121.92 v68.26,121.92
A23  (via drill 0.5 pad 0.3, 0.5 pad 0.81)
  Top 0.305: v145.41,154.62 v149.22,154.62 | v130.18,154.62 130.18,173.35 130.81,173.99 JP5.P$13
  Bottom 0.305: v130.18,154.62 v145.41,154.62 | v149.22,154.62 149.22,145.41 149.86,144.78 MM_C1.158
ALE  (via drill 0.5 pad 0.3)
  Top 0.305: JP3.P$39 29.84,173.99 30.48,173.35 30.48,169.54 62.23,137.79 v62.23,130.49 | v93.34,110.17 v108.58,110.17 | v108.58,102.87 108.58,100.65 108.9,100.33 114.3,100.33 114.94,100.97 MM_C1.77
  Bottom 0.305: v62.23,130.49 65.09,130.49 66.04,129.54 66.04,111.12 66.99,110.17 v93.34,110.17 | v108.58,110.17 v108.58,102.87
B4  (via drill 0.9)
  Top 0.813: 245.11,83.82 U$2.2 | 245.11,83.82 v250.82,83.82 | R2.1 216.96,82.77 218.44,81.28 v218.44,78.11 | v229.24,78.11 243.84,78.11 245.11,79.38 245.11,83.82
  Bottom 0.813: v250.82,83.82 252.73,83.82 254,85.09 B4.1 | v218.44,78.11 v229.24,78.11
BUCHSE
  Top 0.406: R4.1 214.63,64.14 215.9,65.41 226.06,65.41 228.6,62.87 243.21,62.87 245.11,64.77 U$1.2 245.11,67.31 246.38,68.58 252.73,68.58 254,67.31 B6.1
BUCHSEP3.3  (via drill 0.5)
  Top 0.305: D16.A 230.5,50.8 235.5,50.8 D17.C | 252.73,5.71 R48.2 240.03,5.71 | 240.03,5.71 240.03,4.45 239.08,3.49 132.08,3.49 130.81,4.76 v130.81,46.99 | v125.73,62.87 125.73,76.83 127,78.11 IC13.9 129.54,78.11 | 240.03,5.71 240.03,45.72 235.59,50.16 D17.C | D17.C 235.59,50.8
  Bottom 0.305: v130.81,46.99 130.81,60.33 129.54,61.59 126.36,61.59 125.73,62.23 v125.73,62.87
CAN5V  (via drill 0.5)
  Top 0.305: OK1.8 OK1.7 | OK1.8 19.05,93.34 17.78,92.08 17.78,85.72 19.05,84.45 OK2.2 21.59,84.45 22.86,83.19 22.86,76.83 | 22.86,76.83 26.67,76.83 27.94,75.56 27.94,74.3 | OK1.8 20.32,92.08 21.59,90.81 v22.86,90.81 | R50.1 33.66,93.34 v33.66,90.81 | C30.2 27.94,66.67 27.94,70.48 | 27.94,70.48 C29.2 | 27.94,74.3 C27.2 | 27.94,74.3 27.94,70.48 | JP9.2 8.26,66.67 9.53,67.94 15.24,67.94 16.51,69.22 16.51,75.56 17.78,76.83 22.86,76.83 | IC16.3 41.27,99.69 40.64,99.06 37.47,99.06 36.83,98.42 36.83,91.44 v36.2,90.81
  Bottom 0.305: v22.86,90.81 v33.66,90.81 v36.2,90.81
CANGND  (via drill 0.5)
  Top 0.305: OK1.5 16.51,100.97 15.24,99.69 15.24,95.25 13.34,93.34 11.43,93.34 10.16,92.08 CAN.6 9.2,88.57 8.26,87.63 8.26,85.72 9.53,84.45 CAN.3 14.61,82.55 v14.61,80.01 | 26.67,66.67 26.67,71.12 | 26.67,71.12 C29.1 | 26.67,74.3 C27.1 v20.32,74.3 | 26.67,74.3 26.67,71.12 | 26.67,66.67 C30.1 | C31.2 26.67,62.87 v26.67,64.77 | v26.67,64.77 26.67,66.67 | 33.02,74.3 C32.2 36.83,74.3 | 36.83,74.3 39.37,74.3 40.01,73.66 C33.- C34.- 40.64,68.58 40.01,67.94 IC17.2 41.27,64.14 45.72,68.58 45.72,85.72 44.45,87 40.64,87 39.41,88.22 C35.- 39.41,91.48 40.01,92.08 43.81,92.08 | JP8.2 16.51,61.28 v19.05,58.74 32.7,58.74 34.92,60.96 34.92,69.85 36.83,71.75 36.83,74.3 | IC16.2 42.55,103.5 43.18,104.14 44.45,104.14 45.09,103.5 45.09,92.71 44.45,92.08 43.81,92.08 | 43.81,95.89 IC16.8 43.81,92.08 | v26.67,64.77 26.67,74.3
  Bottom 0.305: v20.32,74.3 v14.61,80.01 | v26.67,64.77 26.04,64.77 20,58.74 v19.05,58.74
CCIN2  (via drill 0.5)
  Top 0.305: IC12.2 74.3,60.33 73.66,59.69 71.12,59.69 69.85,60.96 69.85,68.58 71.12,69.85 81.28,69.85 84.45,73.03 84.45,75.56 85.72,76.83 v94.61,76.83 | v112.39,76.83 IC13.13
  Bottom 0.305: v94.61,76.83 v112.39,76.83
CCOUT2  (via drill 0.5, 0.5 pad 0.3)
  Top 0.305: IC12.15 74.3,66.04 73.66,65.41 v71.12,65.41 | v64.77,65.41 v67.94,65.41 | v53.98,83.5 R44.A
  Bottom 0.305: v67.94,65.41 v71.12,65.41 | v64.77,65.41 62.87,65.41 53.98,74.3 v53.98,83.5
D0
  Bottom 0.305: JP3.P$5 71.75,173.99 71.12,173.35 71.12,146.69 72.39,145.41 125.73,145.41 126.36,146.05 126.36,147.96 127.64,149.22 MM_C1.41
D1
  Bottom 0.305: JP3.P$7 69.22,173.99 68.58,173.35 68.58,146.05 69.85,144.78 127,144.78 127.64,145.41 MM_C1.42
D2
  Bottom 0.305: JP3.P$9 66.67,173.99 66.04,173.35 66.04,145.41 67.31,144.15 128.27,144.15 128.91,144.78 128.91,149.22 129.54,149.86 MM_C1.39
D3
  Bottom 0.305: JP3.P$11 64.14,173.99 63.5,173.35 63.5,144.78 64.45,143.51 129.54,143.51 130.18,144.15 MM_C1.40
D4  (via drill 0.5 pad 0.3)
  Top 0.305: L7.2 22.86,39.37 30.48,46.99 42.55,46.99 43.81,48.26 43.81,57.78 57.15,71.12 v57.15,72.71 | v70.48,92.39 70.48,152.4 69.85,153.03 v60.96,153.03
  Bottom 0.305: JP3.P$13 61.59,173.99 60.96,173.35 v60.96,153.03 60.96,144.15 62.23,142.88 130.81,142.88 131.44,143.51 131.44,149.22 132.08,149.86 MM_C1.37 | v70.48,92.39 58.1,92.39 57.15,91.44 v57.15,72.71
D5
  Bottom 0.305: JP3.P$15 59.05,173.99 58.42,173.35 58.42,159.7 60.33,157.8 60.33,155.26 58.42,153.35 58.42,143.51 59.69,142.24 132.08,142.24 132.72,142.88 MM_C1.38
D6
  Bottom 0.305: JP3.P$17 56.52,173.99 55.88,173.35 55.88,160.02 53.98,158.12 53.98,155.26 55.88,153.35 55.88,142.88 57.15,141.6 133.35,141.6 133.99,142.24 133.99,149.22 134.62,149.86 MM_C1.35
D7
  Bottom 0.305: JP3.P$19 53.98,173.99 53.34,173.35 53.34,142.24 54.61,140.97 134.62,140.97 135.25,141.6 MM_C1.36
D8
  Bottom 0.305: JP3.P$21 51.44,173.99 50.8,173.35 50.8,141.6 52.07,140.34 135.89,140.34 136.53,140.97 136.53,149.22 137.16,149.86 MM_C1.33
D9
  Bottom 0.305: JP3.P$23 48.9,173.99 48.26,173.35 48.26,140.97 49.53,139.7 137.16,139.7 137.79,140.34 MM_C1.34
D10
  Bottom 0.305: JP3.P$25 46.35,173.99 45.72,173.35 45.72,140.34 46.99,139.06 138.43,139.06 139.06,139.7 139.06,149.22 139.7,149.86 MM_C1.31
D11
  Bottom 0.305: JP3.P$27 43.81,173.99 43.18,173.35 43.18,139.7 44.45,138.43 139.7,138.43 140.34,139.06 MM_C1.32
D12
  Bottom 0.305: JP3.P$29 41.27,173.99 40.64,173.35 40.64,139.06 41.91,137.79 140.97,137.79 141.6,138.43 141.6,149.22 142.24,149.86 MM_C1.29
D13
  Bottom 0.305: JP3.P$31 38.73,173.99 38.1,173.35 38.1,138.43 39.37,137.16 142.24,137.16 142.88,137.79 MM_C1.30
D14
  Bottom 0.305: JP3.P$33 36.2,173.99 35.56,173.35 35.56,137.79 36.83,136.53 143.51,136.53 144.15,137.16 144.15,149.22 144.78,149.86 MM_C1.27
D15
  Bottom 0.305: JP3.P$35 33.66,173.99 33.02,173.35 33.02,137.16 34.29,135.89 144.78,135.89 145.41,136.53 MM_C1.28
GND  (via drill 0.5, 0.5 pad 0.3, 0.5 pad 0.81, 0.9, 0.9 pad 0.81)  (2 unrouted)
  Top 0.305: 16.51,140.97 C19.1 16.51,141.6 | 16.51,111.76 C22.2 16.51,107.31 17.78,107.31 19.68,105.41 45.72,105.41 46.99,104.14 46.99,67.31 40.64,60.96 36.83,60.96 33.66,57.78 14.61,57.78 | 16.51,111.76 C21.2 | 16.51,141.6 18.41,141.6 19.68,140.34 19.68,130.81 22.23,127.64 22.23,113.67 20.32,111.76 16.51,111.76 | B_GND4.1 B_GND3.1 B_GND2.1 B_GND1.1 243.21,55.24 242.57,55.88 240.66,55.88 D15.A 235.67,55.97 235.59,55.88 | 189.23,23.5 T1.2 | 189.23,23.5 189.23,31.75 191.13,33.66 191.13,44.45 189.87,45.72 | D12.A 215.26,55.24 216.53,53.98 233.68,53.98 235.59,55.88 | 235.59,55.88 D17.A | C24.2 189.23,61.59 187.32,61.59 186.69,62.23 186.69,66.67 187.54,67.53 C25.2 189.23,69.22 189.87,69.85 195.58,69.85 | 195.58,69.85 196.22,69.85 196.85,69.22 196.85,66.67 | 195.58,69.85 v195.58,72.39 | v187.32,23.5 189.23,23.5 | JP10.2 158.12,48.26 155.63,45.77 IC18.10 151.13,45.72 | JP7.1 151.76,73.66 146.05,79.38 129.54,79.38 | 33.02,66.67 C36.1 | 33.02,66.67 33.02,70.48 | 33.02,66.67 33.02,63.5 C37.2 33.23,61.17 31.75,59.69 20.95,59.69 19.05,61.59 JP8.1 19.05,64.77 18.41,65.41 15.88,65.41 14.61,64.14 14.61,57.78 | OK2.5 32.38,79.38 v33.02,78.74 | v34.92,72.39 34.92,71.12 34.29,70.48 33.02,70.48 | 33.02,70.48 C28.2 | JP2.1 5.76,17.2 | 15.03,35.14 15.24,34.92 R26.1 | 15.24,38.73 C23.2 | I2C.8 4.45,50.16 3.17,51.44 3.17,55.88 5.08,57.78 14.61,57.78 | IC8.7 114.3,54.61 v112.39,54.61 | IC7.7 95.25,54.61 v93.98,54.61 | JP1.1 42.55,18.41 43.18,19.05 43.18,27.94 42.55,28.57 JP6.1 | 75.03,54.51 v74.93,54.61 76.2,54.61 IC6.7 | v57.15,52.07 IC5.7 | IC12.3 76.73,61.7 76.83,61.59 IC12.4 78,61.7 78.11,61.59 IC12.5 79.27,61.7 79.38,61.59 IC12.6 80.54,61.7 80.64,61.59 IC12.7 81.81,61.7 81.92,61.59 IC12.8
  Top 0.305: 75.56,61.59 75.56,60.33 73.98,58.74 69.22,58.74 | 69.22,58.74 v69.22,54.61 | IC9.10 81.95,71.8 80.64,70.48 70.48,70.48 69.22,69.22 69.22,58.74 | v86.36,81.28 IC10.10 | v86.36,78.74 83.19,78.74 81.92,77.47 IC9.10 | IC9.10 81.92,73.66 | 16.51,141.6 C18.2 | v106.68,82.87 100.97,82.87 100.01,81.92 100.01,79.69 v99.06,78.74 | 129.54,79.38 IC13.10 | 129.54,79.38 v125.09,79.38 | 179.07,98.74 147.32,98.74 146.69,99.38 146.69,103.5 146.05,104.14 MM_C1.102 MM_C1.99
  Top 0.813: C3.- 240.07,143.55 240.03,143.51 | 240.03,143.51 C8.- | 240.03,143.51 239.81,143.72 | C3.- 240.07,152.44 242.57,154.94 IC1.GND 242.57,161.61 | 242.57,161.61 242.57,165.1 244.16,166.69 B1.VCC- 244.16,171.76 241.94,173.99 LED1.K 236.54,174.94 229.55,174.94 JP4.P$1 JP4.P$3 | 242.57,161.61 v250.19,161.61 | 233.43,149.86 C3.- | v229.11,143.38 229.24,143.51 C4.2 231.56,146.22 233.17,147.83 233.17,149.61 233.43,149.86 | 233.43,149.86 C5.2 | C14.2 237.49,129.54 238.76,128.27 238.76,120.65 236.85,118.75 D11.A 236.22,118.75 236.18,118.7 C10.- 236.22,113.67 233.68,111.12 233.68,107.31 | C12.- IC3.GND 219.71,129.71 L2.2 222.84,132.76 222.88,132.72 222.88,134.62 224.16,135.89 v229.11,135.89 | C12.- | C11.- C12.- | 219.71,106.05 C16.2 | C11.- | 219.71,106.05 C11.- | 219.71,106.05 C15.2 221.4,100.33 | 221.4,100.33 208.91,100.33 195.58,86.68 v195.58,78.11 190.5,78.11 186.06,73.66 179.07,73.66 | 165.74,73.66 165.74,48.9 | 165.74,23.5 v174.62,23.5 | 165.74,48.9 165.74,23.5 | 165.74,23.5 165.74,20.32 162.56,17.14 S4.8 S4.7 S4.6 S4.5 S4.4 S4.3 S4.2 S4.1 133.35,17.14 | 165.74,48.9 JP10.2 | 165.74,73.66 JP7.1 | 179.07,73.66 165.74,73.66 | I2C.8 I2C.6 I2C.4 I2C.2 4.45,40.01 5.71,38.73 C23.2 | 15.24,34.92 15.24,38.73 | R26.1 3.81,34.92 2.54,33.66 2.54,19.05 4.45,17.14 JP2.1 8.26,14.61 BOOT.1 15.56,14.61 17.46,16.51 22.86,16.51 24.77,14.61 RESET.1 29.84,16.51 41.27,16.51 | 41.27,16.51 JP1.1 | 41.27,16.51 41.27,8.89 42.55,7.62 v50.16,7.62 | 233.68,107.31 233.68,106.68 | 233.68,107.31 233.68,100.97 233.04,100.33 225.43,100.33 | 86.36,65.41 104.14,65.41 105.41,64.14 105.41,59.69 | 105.41,59.69 v105.41,54.61
  Top 0.813: 81.92,61.59 75.56,61.59 | 86.36,65.41 IC11.8 | 133.35,17.14 133.35,46.99 120.65,59.69 105.41,59.69 | 133.35,17.14 v133.35,9.53 | MM_C1.128 MM_C1.127 178.44,101.28 179.07,100.65 179.07,98.74 179.07,73.66 | IC12.8 82.65,61.7 86.36,65.41 | 76.2,173.99 v76.2,149.86 | JP3.P$1 76.2,173.99 | JP3.P$3 76.2,173.99 | 221.4,100.33 225.43,100.33 | 225.43,100.33 v225.43,98.74
  Bottom 0.305: T1.2 T1.4 T2.2 T2.4 T3.2 T3.4 234.31,19.68 236.22,17.78 B_GND4.1 | v195.58,72.39 v195.58,78.11 | v174.62,23.5 v187.32,23.5 | v33.02,78.74 33.02,74.3 v34.92,72.39 | v112.39,54.61 v105.41,54.61 v93.98,54.61 | v74.93,54.61 v69.22,54.61 69.22,52.7 68.58,52.07 v57.15,52.07 | v86.36,81.28 v86.36,78.74 v99.06,78.74 | MM_C1.63 MM_C1.61 | MM_C1.73 109.86,86.04 v106.68,82.87 | MM_C1.84 122.56,103.5 123.83,102.23 123.83,80.64 v125.09,79.38
  Bottom 0.813: B3.1 254,160.34 252.73,161.61 v250.19,161.61 | v229.11,135.89 v229.11,143.38 | v50.16,7.62 53.98,7.62 KIPP1.2 KIPP2.2 KIPP3.2 KIPP4.2 KIPP5.2 KIPP6.2 KIPP7.2 KIPP8.2 v133.35,9.53 | JP5.P$1 JP5.P$3 144.15,177.16 | JP4.P$3 226.06,176.21 225.11,177.16 144.15,177.16 | JP3.P$3 JP3.P$1 77.47,176.21 78.42,177.16 144.15,177.16 | MM_C1.64 MM_C1.63 v76.2,149.86
N  (via drill 0.5)
  Top 0.305: B_P7.5.1 254,32.38 256.54,29.84 262.89,29.84 264.8,27.94 264.8,3.81 262.89,1.91 130.81,1.91 129.54,3.17 v129.54,48.26 | v122.56,64.14 122.56,74.3 121.28,75.56 IC13.14 119.38,75.56
  Bottom 0.305: v129.54,48.26 129.54,59.05 128.27,60.33 123.83,60.33 122.56,61.59 v122.56,64.14
N$3
  Top 0.813: R1.S 262.89,117.47 261.62,118.75 IC4.1
N$4
  Top 0.406: R6.S U$1.1
N$5
  Top 0.305: S1.P$3 189.84,36.22 186.06,40.01 IC14.4 184.89,45.82 184.78,45.72 IC14.3
N$6
  Top 0.813: 249.56,109.22 D6.C R1.A
N$7
  Top 0.813: D7.A R1.E
N$8
  Top 0.813: C2.+ 244.47,124.59 247.52,127.64 250.19,127.64 | 250.19,127.64 R3.1 | 250.19,127.64 C7.1 | IC2.OUT 257.18,127.64 250.19,127.64
N$9
  Top 0.813: D5.C 244.47,113.03 244.47,109.31 D6.A
N$10
  Top 0.406: R5.S 233.68,90.81 234.95,92.08 246.38,92.08 247.65,90.81 U$2.1
N$11
  Top 0.813: D10.A 236.22,125.09 234.95,126.36 233.17,126.36 | L1.2 233.17,126.36 | C14.1 233.17,129.5 233.17,126.36
N$12
  Top 0.813: 231.14,113.67 231.06,113.75 D11.C 231.14,118.75 231.06,118.83 D10.C | 231.14,113.67 C10.+ | C15.1 223.1,117.26 | 223.1,117.26 IC3.IN | 223.1,117.26 223.1,113.67 231.14,113.67
N$13
  Top 0.813: D7.C 244.47,104.14 244.47,100.42 D8.A
N$14  (1 unrouted)
  Top 0.305: C22.1 16.51,105.41 11.61,105.41 | RS232_2.G2 8.71,130.63 6.99,128.91 6.99,107.31 8.89,105.41 11.43,105.41 RS232_2.G1
N$15
  Top 0.813: R7.1 LED1.A
N$16
  Top 0.305: 16.51,123.83 C20.2 16.51,123.19 16.1,123.6 RS232_2.5
N$17  (via drill 0.9 pad 0.81)
  Top 0.813: B1.VCC+ 250.88,174.57 252.41,173.04 252.41,164.78 251.14,163.51 v245.43,163.51 | v238.12,163.51 234.63,163.51 230.82,159.7 226.69,159.7 226.31,159.64 225.11,159.64 | F2.1A 225.11,159.64 | 225.11,159.64 225.11,159.7
  Bottom 0.813: v238.12,163.51 v245.43,163.51
N$18
  Top 0.305: C19.2 16.09,139.06 11.43,139.06 | 11.43,139.06 RS232_1.G1 | 11.43,139.06 8.89,139.06 6.99,140.97 6.99,162.56 8.89,164.47 11.43,164.47 RS232_1.G2
N$19
  Top 0.305: RS232_1.2 16.51,149.02 | 16.51,149.02 16.51,149.22 L3.2 | 16.51,149.02 C18.1
N$20
  Top 0.305: C17.2 16.51,157.48 16.51,157.25 RS232_1.5
N$21
  Top 0.305: L4.2 16.51,155.57 C17.1 16.51,153.03 15.24,151.76 RS232_1.3
N$22
  Top 0.305: IC5.1 64.77,52.7 62.87,50.8 56.52,50.8 55.88,50.16 55.88,45.72 59.69,41.91 59.69,34.29 | 59.69,34.29 59.69,8.26 57.78,6.99 KIPP1.1 | 59.69,34.29 R10.1
N$23
  Top 0.305: 60.96,54.61 60.96,55.56 59.69,56.83 55.56,56.83 50.16,51.44 50.16,24.45 51.44,23.18 51.44,20.95 52.7,19.68 55.88,19.68 SCHIEB1.P$1 | 60.96,54.61 IC5.4 | IC5.3 61.06,54.51 60.96,54.61
N$24  (1 unrouted)
  Top 0.305: KIPP1.3 57.15,12.06 58.42,13.34 58.42,24.77 57.05,26.14 56.83,26.14 | IC5.5 59.69,55.56 59.05,56.2 56.2,56.2 50.8,50.8 50.8,27.3 52.04,26.06 55.85,26.06 55.88,26.04 | 55.88,26.04 SCHIEB1.P$3 | 56.83,26.14 55.98,26.14 55.88,26.04 | 56.83,26.14 56.83,26.04 | 56.73,26.14 R9.1
N$25
  Top 0.305: IC5.2 63.5,53.34 62.87,52.7 59.05,52.7 58.42,53.34 IC5.6 58.42,54.61
N$26  (via drill 0.5)
  Top 0.305: IC5.9 58.42,45.09 v59.05,44.45 | v67.31,44.45 69.22,42.55 69.22,34.29 | 69.22,34.29 69.22,8.26 67.94,6.99 KIPP2.1 | 69.22,34.29 R12.1
  Bottom 0.305: v67.31,44.45 v59.05,44.45
N$27
  Top 0.305: KIPP2.3 66.67,12.06 67.94,13.34 67.94,24.77 66.67,26.04 | SCHIEB2.P$3 65.41,26.04 65.72,26.04 | 66.67,26.04 66.04,26.04 | 66.04,26.04 65.72,26.04 | 63.5,48.9 IC5.13 63.5,46.99 61.59,45.09 61.59,27.3 62.84,26.06 SCHIEB2.P$3 | 65.72,26.04 65.7,26.06 SCHIEB2.P$3 | 66.67,26.04 66.57,26.14 | R11.1 66.25,26.25 66.04,26.04
N$28
  Top 0.305: 57.15,48.26 IC5.8 57.15,49.53 57.78,50.16 61.59,50.16 62.23,49.53 IC5.12 62.23,46.99 60.64,45.4 60.64,20.95 61.94,19.66 SCHIEB2.P$1
N$29
  Top 0.305: IC5.10 59.69,48.26 59.79,48.36 IC5.11
N$30
  Top 0.305: KIPP3.1 77.47,6.99 78.74,8.26 78.74,34.29 | IC6.1 83.82,52.07 83.19,51.44 74.93,51.44 74.3,50.8 74.3,45.72 78.74,41.27 78.74,34.29 | 78.74,34.29 R14.1
N$31
  Top 0.305: KIPP3.3 76.2,12.06 77.47,13.34 77.47,24.77 76.2,26.04 | 76.2,26.04 74.93,26.04 SCHIEB3.P$3 72.36,26.06 71.12,27.3 71.12,53.98 74.3,57.15 78.11,57.15 78.74,56.52 IC6.5 | R13.1 75.88,31.11 75.88,26.04 76.2,26.04
N$32
  Top 0.305: IC6.3 81.28,54.61 80.01,54.61 | 79.91,54.51 IC6.4 80.01,54.61 | 80.01,54.61 80.01,56.52 78.74,57.78 73.66,57.78 70.17,53.98 70.17,20.95 71.44,19.68 74.93,19.68 SCHIEB3.P$1
N$33
  Top 0.305: IC6.6 77.47,53.34 78.11,52.7 81.92,52.7 82.55,53.34 IC6.2 82.55,54.61
N$34
  Top 0.305: L7.1 22.86,32.38 22.23,31.75 R25.1
N$35  (via drill 0.5)
  Top 0.305: KIPP4.1 87,6.99 88.27,8.26 88.27,34.29 | 88.27,34.29 88.27,41.91 v86.36,43.81 | v78.11,43.81 77.47,44.45 IC6.9 | 88.27,34.29 R16.1
  Bottom 0.305: v86.36,43.81 v78.11,43.81
N$36
  Top 0.305: KIPP4.3 85.72,12.06 87,13.34 87,24.77 85.72,26.04 85.41,26.04 | 85.41,26.04 84.45,26.04 SCHIEB4.P$3 81.89,26.06 80.64,27.3 80.64,45.09 82.55,46.99 IC6.13 | R15.1 85.31,26.14 85.41,26.04
N$37
  Top 0.305: IC6.8 76.2,49.53 76.83,50.16 80.64,50.16 81.28,49.53 IC6.12 81.28,46.99 79.69,45.4 79.69,20.95 80.96,19.68 84.45,19.68 SCHIEB4.P$1
N$38
  Top 0.305: IC6.10 78.74,48.26 78.84,48.36 IC6.11
N$39
  Top 0.305: IC7.1 102.87,52.7 101.6,51.44 93.98,51.44 93.34,50.8 93.34,45.72 97.79,41.27 97.79,34.29 | 97.79,34.29 97.79,8.26 96.52,6.99 KIPP5.1 | 97.79,34.29 R18.1
N$40
  Top 0.305: KIPP5.3 95.25,12.06 96.52,13.34 96.52,24.77 95.25,26.04 | 95.25,26.04 93.98,26.04 SCHIEB5.P$3 91.47,26.06 91.44,26.04 90.17,27.3 90.17,53.98 93.34,57.15 97.16,57.15 97.79,56.52 IC7.5 | R17.1 94.83,26.14 95.25,26.04
N$41
  Top 0.305: IC7.3 100.33,54.61 100.23,54.51 IC7.4 99.06,57.78 98.42,58.42 93.34,58.42 89.22,54.29 89.22,20.95 90.49,19.68 93.98,19.68 SCHIEB5.P$1
N$42
  Top 0.305: IC7.2 101.6,53.34 100.97,52.7 97.16,52.7 96.52,53.34 IC7.6 96.52,54.61
N$43  (via drill 0.5)
  Top 0.305: IC7.9 96.52,44.45 v97.16,43.81 | v105.41,43.81 107.31,41.91 107.31,34.29 | 107.31,34.29 107.31,8.26 106.05,6.99 KIPP6.1 | 107.31,34.29 R20.1
  Bottom 0.305: v105.41,43.81 v97.16,43.81
N$44
  Top 0.305: KIPP6.3 104.78,12.06 106.05,13.34 106.05,24.77 104.78,26.04 104.46,26.04 | 104.46,26.04 103.5,26.04 SCHIEB6.P$3 100.94,26.06 99.69,27.3 99.69,45.09 101.6,46.99 IC7.13 | R19.1 104.36,26.14 104.46,26.04
N$45
  Top 0.305: 100.33,48.26 100.33,46.99 98.74,45.4 98.74,20.95 100.01,19.68 103.5,19.68 SCHIEB6.P$1 | IC7.8 95.25,49.53 95.89,50.16 99.69,50.16 100.33,49.53 100.33,48.26 | 100.33,48.26 IC7.12
N$46
  Top 0.305: IC7.10 97.79,48.26 97.89,48.36 IC7.11
N$47
  Top 0.305: KIPP7.1 115.57,6.99 116.84,8.26 116.84,34.29 | 116.84,34.29 116.84,41.27 112.39,45.72 112.39,50.8 113.03,51.44 120.65,51.44 121.92,52.7 IC8.1 121.92,54.61 | 116.84,34.29 R22.1
N$48
  Top 0.305: KIPP7.3 114.3,12.06 115.57,13.34 115.57,24.77 114.3,26.04 113.98,26.04 | 113.98,26.04 113.03,26.04 SCHIEB7.P$3 110.47,26.06 109.22,27.3 109.22,53.98 112.39,57.15 116.2,57.15 116.84,56.52 IC8.5 | R21.1 113.88,26.14 113.98,26.04
N$49
  Top 0.305: IC8.3 119.38,54.61 119.28,54.51 IC8.4 118.11,57.78 117.47,58.42 112.39,58.42 108.27,54.29 108.27,20.95 109.54,19.68 113.03,19.68 SCHIEB7.P$1
N$50
  Top 0.305: IC8.2 120.65,53.34 120.02,52.7 116.2,52.7 115.57,53.34 IC8.6 115.57,54.61
N$53  (via drill 0.5)
  Top 0.305: IC8.9 115.57,44.45 v116.2,43.81 | v124.46,43.81 128.27,40.01 128.27,34.29 | 128.27,34.29 128.27,8.26 127,6.99 KIPP8.1 | 128.27,34.29 R24.1
  Bottom 0.305: v124.46,43.81 v116.2,43.81
N$54
  Top 0.305: KIPP8.3 123.83,12.06 125.09,13.34 125.09,24.77 123.83,26.04 123.51,26.04 | 123.51,26.04 122.56,26.04 SCHIEB8.P$3 119.99,26.06 118.75,27.3 118.75,45.09 120.65,46.99 120.65,48.9 IC8.13 | R23.1 123.41,26.14 123.51,26.04
N$55
  Top 0.305: IC8.8 114.3,49.53 114.94,50.16 118.75,50.16 119.38,49.53 IC8.12 | IC8.12 119.38,48.26 | IC8.12 119.38,46.99 117.79,45.4 117.79,20.95 119.06,19.68 122.56,19.68 SCHIEB8.P$1
N$56
  Top 0.305: IC8.10 116.84,48.26 116.94,48.36 IC8.11
N$57  (via drill 0.5)
  Top 0.305: v50.16,22.86 49.53,23.5 49.53,52.07 69.22,71.75 71.12,71.75 71.75,72.39 71.75,73.66 71.77,73.67 IC9.2
  Bottom 0.305: SCHIEB1.P$2 v50.17,22.86 v50.16,22.86
N$58  (via drill 0.5)
  Top 0.305: IC9.3 73.06,75.53 72.39,76.2 70.48,76.2 67.31,73.03 67.31,71.12 48.9,52.7 48.9,22.23 v50.16,20.95
  Bottom 0.305: v50.16,20.95 60.33,20.95 62.23,22.86 SCHIEB2.P$2
N$59  (via drill 0.5)
  Top 0.305: IC9.4 74.33,75.53 73.03,76.83 69.85,76.83 66.04,73.03 66.04,71.12 48.26,53.34 48.26,20.32 49.53,19.05 v50.16,19.05
  Bottom 0.305: v50.16,19.05 50.8,18.41 67.94,18.41 72.39,22.86 SCHIEB3.P$2
N$60  (via drill 0.5)
  Top 0.305: IC9.5 75.61,75.53 73.66,77.47 69.22,77.47 64.77,73.03 64.77,71.12 47.62,53.98 47.62,18.41 48.9,17.14 v50.16,17.14
  Bottom 0.305: v50.16,17.14 50.8,17.78 79.38,17.78 SCHIEB4.P$2
N$61  (via drill 0.5)
  Top 0.305: IC9.9 80.69,75.53 76.2,80.01 66.67,80.01 59.69,73.03 59.69,71.12 45.09,56.52 45.09,10.79 46.35,9.53 v50.16,9.53
  Bottom 0.305: v50.16,9.53 55.88,15.24 114.94,15.24 SCHIEB8.P$2
N$62  (via drill 0.5)
  Top 0.305: IC9.8 79.42,75.53 75.56,79.38 67.31,79.38 60.96,73.03 60.96,71.12 45.72,55.88 45.72,12.7 46.99,11.43 v50.16,11.43
  Bottom 0.305: v50.16,11.43 54.61,15.88 106.05,15.88 SCHIEB7.P$2
N$63  (via drill 0.5)
  Top 0.305: IC9.7 78.14,75.53 74.93,78.74 67.94,78.74 62.23,73.03 62.23,71.12 46.35,55.24 46.35,14.61 47.62,13.34 v50.16,13.34
  Bottom 0.305: v50.16,13.34 53.34,16.51 97.16,16.51 SCHIEB6.P$2
N$64  (via drill 0.5)
  Top 0.305: IC9.6 76.88,75.53 74.3,78.11 68.58,78.11 63.5,73.03 63.5,71.12 46.99,54.61 46.99,16.51 48.26,15.24 v50.16,15.24
  Bottom 0.305: v50.16,15.24 52.07,17.14 88.27,17.14 SCHIEB5.P$2
N$65  (via drill 0.5, 0.5 pad 0.41)
  Top 0.305: JP1.2 39.37,20.95 38.31,22.01 R8.1 38.1,40.64 38.1,41.91 v38.73,42.55 | IC9.19 71.8,83.78 71.75,83.82 v71.75,86.36 | IC9.1 70.48,73.66 v69.22,73.66
  Bottom 0.305: v38.73,42.55 56.52,60.33 64.77,60.33 66.04,61.59 66.04,67.31 69.22,70.48 v69.22,73.66 69.22,85.41 70.17,86.36 v71.75,86.36 72.07,86.36
N$66
  Top 0.305: 5.76,19.73 JP2.2 BOOT.2 13.34,19.68 15.24,21.59 15.24,31.75 R25.2
N$67
  Top 0.406: RESET.2 31.75,19.68 33.02,20.95 L9.1 33.02,32.38
N$68
  Top 0.305: L9.2 32.98,36.24 L8.1
  Top 0.406: L9.2 33.02,36.2 32.98,36.24
N$69  (1 unrouted)
  Top 0.305: IC14.6 188.59,47.62 187.96,48.26 184.15,48.26 183.51,47.62 183.51,46.35
N$70
  Top 0.305: 96.52,80.01 97.16,80.01 97.79,80.64 IC10.1 97.79,83.82 | 96.52,80.01 IC10.19 96.52,68.58 97.37,67.73 R27.1 | 96.52,80.01 77.47,80.01 76.83,80.64 66.04,80.64 58.42,73.03 58.42,71.12 44.45,57.15 44.45,36.83 43.18,35.56 40.64,35.56 39.37,34.29 39.37,26.67 40.01,26.04 JP6.2
N$71
  Top 0.305: IC11.1 IC10.18
N$72
  Top 0.305: IC11.2 IC10.17
N$73
  Top 0.305: IC11.3 IC10.16
N$74
  Top 0.305: IC11.4 IC10.15
N$75
  Top 0.305: IC11.5 IC10.14
N$76
  Top 0.305: IC11.6 IC10.13
N$77
  Top 0.305: IC11.7 IC10.12
N$78
  Top 0.305: IC12.1 73.03,63.5 74.3,64.77 82.55,64.77 84.45,66.67 84.45,68.58 86.36,70.48 IC10.11
N$79
  Top 0.305: IC14.1 182.25,41.91 186.06,38.1 186.06,17.78 T1.1 192.41,11.43 192.41,9.21 194.31,7.3 218.76,7.3 220.34,8.89 220.34,40.42 R37.1
N$80
  Top 0.305: LED2.A 56.83,40.64 56.83,37.47 R35.1
N$81
  Top 0.305: LED3.A 66.36,40.64 66.36,37.47 R34.1
N$82
  Top 0.305: LED4.A 76.2,40.64 76.2,37.47 R33.1
N$83
  Top 0.305: LED5.A 85.41,40.64 85.41,37.47 R32.1
N$84
  Top 0.305: LED6.A 94.93,40.32 94.93,37.47 R31.1
N$85
  Top 0.305: LED7.A 104.46,40.32 104.46,37.47 R30.1
N$86
  Top 0.305: LED8.A 113.98,40.32 113.98,37.47 R29.1
N$87
  Top 0.305: LED9.A 123.51,40.32 123.51,37.47 R28.1
N$88  (via drill 0.5)
  Top 0.305: IC12.16 73.03,67.94 v71.12,67.94 | v52.07,40.64 LED2.C
  Bottom 0.305: v71.12,67.94 67.94,67.94 66.67,66.67 66.67,60.96 65.41,59.69 57.15,59.69 54.61,57.15 54.61,46.35 52.07,45.09 v52.07,40.64
N$89  (via drill 0.5)
  Top 0.305: IC11.10 87.63,62.87 87,63.5 85.72,63.5 85.09,62.87 v85.09,59.69 | LED3.C 64.66,42.11 66.04,43.5 v66.04,46.35
  Bottom 0.305: v85.09,59.69 85.09,59.05 87.63,56.52 87.63,47.62 86.36,46.35 v66.04,46.35
N$90  (via drill 0.5)
  Top 0.305: IC11.11 88.9,60.96 v87.63,59.69 | v72.39,40.64 LED4.C
  Bottom 0.305: v87.63,59.69 87.63,58.42 88.9,57.15 88.9,47.62 86.36,45.09 73.66,45.09 72.39,43.81 v72.39,40.64
N$91  (via drill 0.5)
  Top 0.305: IC11.12 90.17,60.33 v89.53,59.69 | LED5.C 83.7,41.8 v83.82,41.91
  Bottom 0.305: v89.53,59.69 89.53,58.42 90.17,57.78 90.17,42.86 89.22,41.91 v83.82,41.91
N$94  (via drill 0.5)
  Top 0.305: v91.44,59.69 IC11.13 | LED6.C v91.44,40.32
  Bottom 0.305: v91.44,40.32 v91.44,59.69
N$95  (via drill 0.5)
  Top 0.305: IC11.14 92.71,60.33 v93.34,59.69 | LED7.C 102.87,40.32 v102.87,41.59
  Bottom 0.305: v93.34,59.69 93.34,57.78 92.71,57.15 92.71,42.23 93.34,41.59 v102.87,41.59
N$96  (via drill 0.5)
  Top 0.305: IC11.15 93.98,60.96 v95.25,59.69 | v110.17,40.32 LED8.C
  Bottom 0.305: v95.25,59.69 95.25,57.15 95.89,56.52 113.03,56.52 114.3,55.24 114.3,45.72 113.67,45.09 110.81,45.09 110.17,44.45 v110.17,40.32
N$97  (via drill 0.5)
  Top 0.305: IC11.16 95.25,62.87 95.89,63.5 96.52,63.5 97.16,62.87 v97.16,59.69 | LED9.C 121.81,41.8 v121.92,41.91
  Bottom 0.305: v97.16,59.69 97.16,57.78 97.79,57.15 117.47,57.15 125.73,48.9 125.73,42.86 124.78,41.91 v121.92,41.91
N$98  (via drill 0.5)
  Top 0.305: v193.04,31.11 S1.P$2 | IC13.3 149.22,70.48 v152.72,66.99
  Bottom 0.305: v193.04,31.11 188.59,31.11 v152.72,66.99
N$103
  Top 0.305: IC15.5 192.98,60.9 191.77,59.69 189.23,59.69 C24.1
N$104
  Top 0.305: R38.1 220.98,43.18 222.25,41.91 222.25,7.94 220.66,6.35 187.32,6.35 184.78,8.89 184.78,36.83 179.71,41.91 179.71,53.98 182.25,56.52 193.04,56.52 194.31,57.78 IC15.6 194.31,60.96 | IC15.7 195.58,60.96 194.31,60.96 | 194.31,60.96 194.31,62.23 193.68,62.87 189.87,62.87 189.23,63.5 C25.1 189.23,66.04
N$105  (via drill 0.5)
